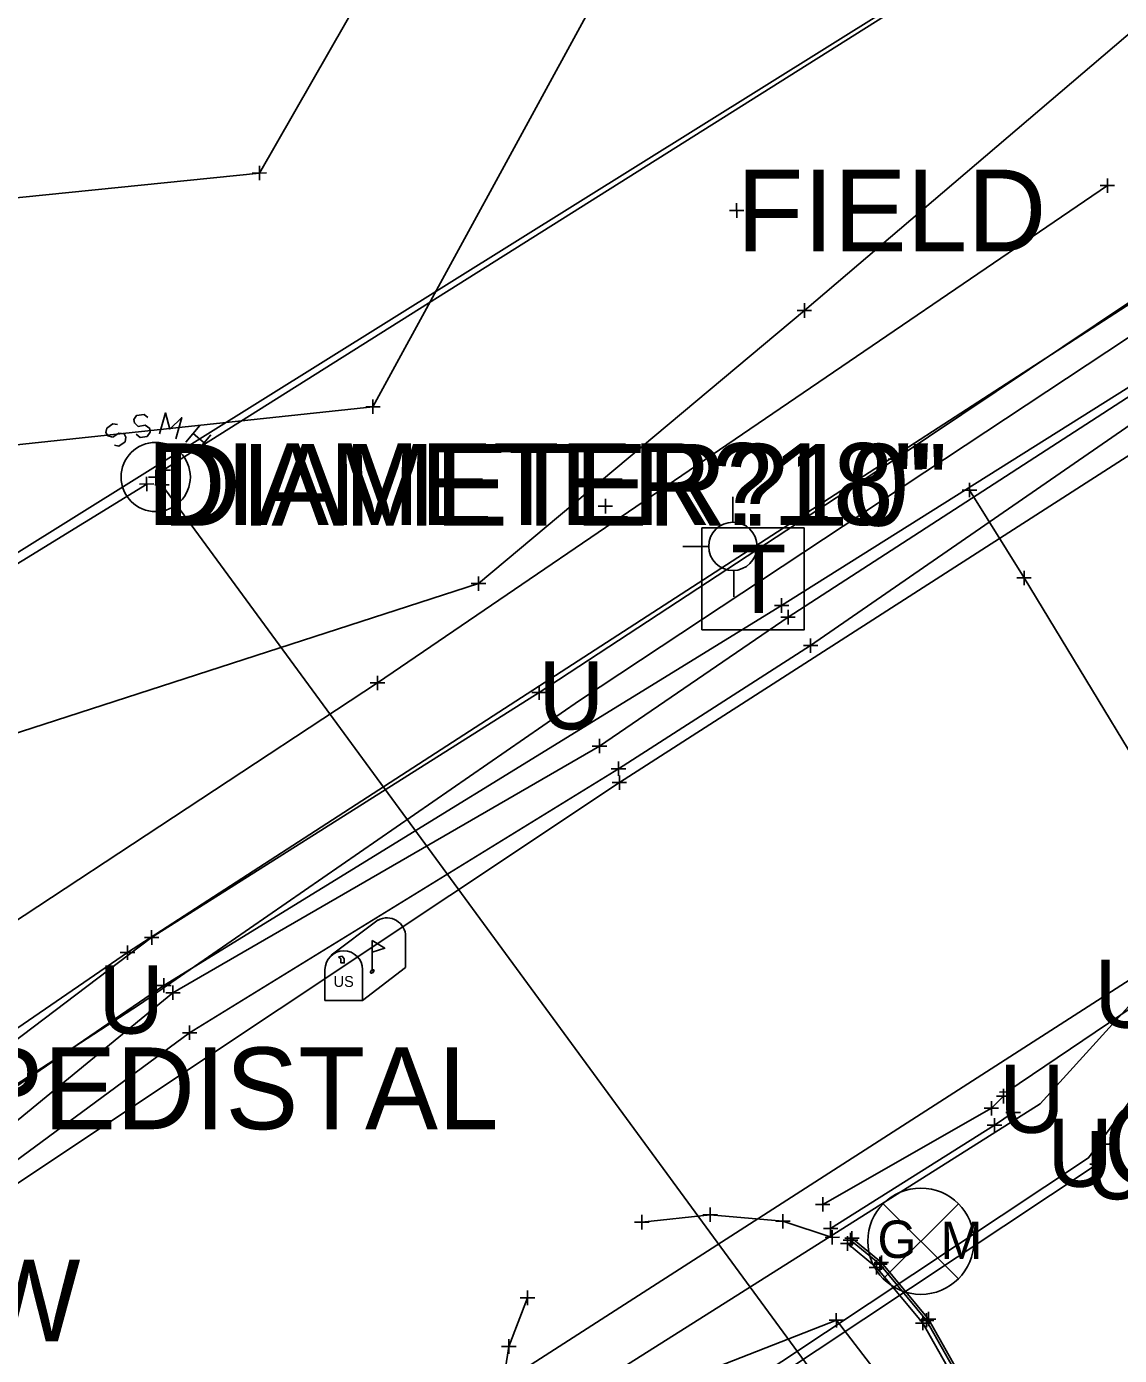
# Model space of a CAD drawing. Extents: x -1 to 1157254, y -1 to 2021979.
# Drawn here: x 1150680.9 to 1150777.1, y 2019897 to 2020014.1 of the extents above; entities that cross this region are included whole.
import ezdxf

# ---------------------------------------------------------------- set-up
doc = ezdxf.new("R2010")
doc.units = 0
for name, color, linetype in [('S_BUILDING_ANNOT', 7, 'Continuous'), ('S_CAL_CORNER_ANNOT', 7, 'Continuous'), ('S_CATCH_BASIN', 7, 'Continuous'), ('S_CATCH_BASIN_ANNOT', 7, 'Continuous'), ('S_CONTOUR_ANNOT', 7, 'Continuous'), ('S_CONTOUR_MAJOR', 7, 'Continuous'), ('S_CONTOUR_MINOR', 7, 'Continuous'), ('S_CROSS_DRAIN', 7, 'Continuous'), ('S_CTL_TABLE', 7, 'Continuous'), ('S_DRIVEWAY_ANNOT', 7, 'Continuous'), ('S_DROP_INLET', 7, 'Continuous'), ('S_DROP_INLET_ANNOT', 7, 'Continuous'), ('S_EDGE_BITUMINOUS_ANNOT', 7, 'Continuous'), ('S_EDGE_PAVEMENT', 7, 'Continuous'), ('S_EDGE_PAVEMENT_ANNOT', 7, 'Continuous'), ('S_ENV_CONSTRAINT', 7, 'Continuous'), ('S_FENCE', 7, 'Continuous'), ('S_GATE', 7, 'Continuous')]:
    doc.layers.add(name, color=color, linetype=linetype)

msp = doc.modelspace()

# ---------------------------------------------------------------- linework, layer by layer
at = {"layer": 'S_BUILDING_ANNOT'}
for p, q in [((1150775.44, 2020000.06), (1150776.71, 2020000.06)), ((1150776.08, 2019999.42), (1150776.07, 2020000.69)), ((1150776.08, 2020000.06), (1150776.08, 2020000.06)), ((1150742.78, 2019997.87), (1150744.05, 2019997.88)), ((1150743.42, 2019997.24), (1150743.41, 2019998.51)), ((1150743.41, 2019997.88), (1150743.41, 2019997.88)), ((1150692.89, 2019974.36), (1150692.89, 2019975.64)), ((1150692.89, 2019974.36), (1150692.89, 2019975.64)), ((1150691.44, 2019973.15), (1150691.43, 2019974.42)), ((1150691.44, 2019973.15), (1150691.43, 2019974.42)), ((1150691.59, 2019974.39), (1150692.87, 2019974.4)), ((1150692.23, 2019973.76), (1150692.23, 2019975.03)), ((1150692.23, 2019974.4), (1150692.23, 2019974.4)), ((1150692.25, 2019975), (1150693.53, 2019975)), ((1150692.25, 2019975), (1150693.53, 2019975)), ((1150692.78, 2019973.07), (1150692.77, 2019974.34)), ((1150692.78, 2019973.07), (1150692.77, 2019974.34)), ((1150692.89, 2019975), (1150692.89, 2019975)), ((1150692.89, 2019975), (1150692.89, 2019975)), ((1150690.8, 2019973.78), (1150692.07, 2019973.79)), ((1150690.8, 2019973.78), (1150692.07, 2019973.79)), ((1150691.44, 2019973.78), (1150691.44, 2019973.78)), ((1150691.44, 2019973.78), (1150691.44, 2019973.78)), ((1150692.14, 2019973.7), (1150693.41, 2019973.71)), ((1150692.14, 2019973.7), (1150693.41, 2019973.71)), ((1150692.78, 2019973.71), (1150692.78, 2019973.71)), ((1150692.78, 2019973.71), (1150692.78, 2019973.71)), ((1150763.28, 2019973.24), (1150764.56, 2019973.24)), ((1150763.92, 2019972.61), (1150763.92, 2019973.88)), ((1150763.92, 2019973.24), (1150763.92, 2019973.24)), ((1150731.21, 2019971.84), (1150732.48, 2019971.84)), ((1150731.85, 2019971.2), (1150731.85, 2019972.48)), ((1150731.85, 2019971.84), (1150731.85, 2019971.84)), ((1150768.74, 2019964.87), (1150768.73, 2019966.14)), ((1150768.1, 2019965.51), (1150769.37, 2019965.51)), ((1150768.74, 2019965.51), (1150768.74, 2019965.51)), ((1150747.37, 2019962.45), (1150747.37, 2019963.72)), ((1150746.74, 2019963.08), (1150748.01, 2019963.09)), ((1150747.37, 2019963.08), (1150747.37, 2019963.08)), ((1150747.94, 2019961.42), (1150747.94, 2019962.69)), ((1150747.3, 2019962.05), (1150748.57, 2019962.05)), ((1150747.94, 2019962.05), (1150747.94, 2019962.05)), ((1150749.93, 2019958.92), (1150749.93, 2019960.19)), ((1150749.3, 2019959.55), (1150750.57, 2019959.56)), ((1150749.93, 2019959.55), (1150749.93, 2019959.55)), ((1150711.77, 2019955.62), (1150711.77, 2019956.89)), ((1150711.13, 2019956.26), (1150712.41, 2019956.26)), ((1150711.77, 2019956.26), (1150711.77, 2019956.26)), ((1150730.69, 2019950.7), (1150731.96, 2019950.7)), ((1150731.33, 2019950.07), (1150731.32, 2019951.34)), ((1150731.32, 2019950.7), (1150731.32, 2019950.7)), ((1150732.37, 2019948.71), (1150733.64, 2019948.71)), ((1150733, 2019948.07), (1150733, 2019949.34)), ((1150733, 2019948.71), (1150733, 2019948.71)), ((1150732.45, 2019947.48), (1150733.72, 2019947.48)), ((1150733.09, 2019946.84), (1150733.09, 2019948.12)), ((1150733.09, 2019947.48), (1150733.09, 2019947.48)), ((1150689.74, 2019931.88), (1150689.74, 2019933.15)), ((1150689.11, 2019932.52), (1150690.38, 2019932.52)), ((1150689.74, 2019932.52), (1150689.74, 2019932.52)), ((1150692.3, 2019929.63), (1150693.58, 2019929.63)), ((1150692.94, 2019928.99), (1150692.94, 2019930.27)), ((1150692.94, 2019929.63), (1150692.94, 2019929.63)), ((1150693.75, 2019928.34), (1150693.75, 2019929.61)), ((1150693.12, 2019928.98), (1150694.39, 2019928.98)), ((1150693.75, 2019928.98), (1150693.75, 2019928.98)), ((1150695.22, 2019924.82), (1150695.21, 2019926.1)), ((1150694.58, 2019925.46), (1150695.85, 2019925.46)), ((1150695.21, 2019925.46), (1150695.21, 2019925.46)), ((1150766.58, 2019920.23), (1150767.85, 2019920.24)), ((1150766.93, 2019919.23), (1150766.93, 2019920.5)), ((1150767.22, 2019919.6), (1150767.22, 2019920.87)), ((1150767.22, 2019920.24), (1150767.22, 2019920.24)), ((1150765.86, 2019918.16), (1150765.86, 2019919.43)), ((1150766.29, 2019919.86), (1150767.56, 2019919.87)), ((1150766.93, 2019919.86), (1150766.93, 2019919.86)), ((1150767.77, 2019917.79), (1150767.77, 2019919.07)), ((1150765.22, 2019918.8), (1150766.49, 2019918.8)), ((1150765.86, 2019918.8), (1150765.86, 2019918.8)), ((1150766.12, 2019916.66), (1150766.12, 2019917.93)), ((1150767.14, 2019918.43), (1150768.41, 2019918.43)), ((1150767.77, 2019918.43), (1150767.77, 2019918.43)), ((1150765.48, 2019917.3), (1150766.76, 2019917.3)), ((1150766.12, 2019917.3), (1150766.12, 2019917.3)), ((1150775.11, 2019915.65), (1150776.38, 2019915.65)), ((1150775.74, 2019915.01), (1150775.74, 2019916.29)), ((1150775.74, 2019915.65), (1150775.74, 2019915.65)), ((1150775.16, 2019913.25), (1150775.16, 2019914.52)), ((1150774.52, 2019913.88), (1150775.79, 2019913.88)), ((1150775.16, 2019913.88), (1150775.16, 2019913.88)), ((1150750.99, 2019909.71), (1150750.99, 2019910.98)), ((1150741.08, 2019908.79), (1150741.08, 2019910.06)), ((1150750.35, 2019910.34), (1150751.63, 2019910.34)), ((1150750.99, 2019910.34), (1150750.99, 2019910.34)), ((1150734.42, 2019908.77), (1150735.69, 2019908.77)), ((1150735.06, 2019908.13), (1150735.06, 2019909.41)), ((1150735.06, 2019908.77), (1150735.06, 2019908.77)), ((1150740.44, 2019909.43), (1150741.71, 2019909.43)), ((1150741.08, 2019909.43), (1150741.08, 2019909.43)), ((1150746.86, 2019908.85), (1150748.13, 2019908.86)), ((1150747.49, 2019908.22), (1150747.49, 2019909.49)), ((1150747.49, 2019908.85), (1150747.49, 2019908.85)), ((1150751.69, 2019907.59), (1150751.69, 2019908.86)), ((1150751.05, 2019908.22), (1150752.32, 2019908.22)), ((1150751.2, 2019907.43), (1150752.47, 2019907.44)), ((1150751.69, 2019908.22), (1150751.69, 2019908.22)), ((1150751.84, 2019906.8), (1150751.83, 2019908.07)), ((1150751.84, 2019907.43), (1150751.84, 2019907.43)), ((1150752.94, 2019907.35), (1150754.21, 2019907.35)), ((1150753.19, 2019906.25), (1150753.19, 2019907.53)), ((1150753.45, 2019906.56), (1150753.45, 2019907.83)), ((1150753.58, 2019906.72), (1150753.57, 2019907.99)), ((1150753.57, 2019907.35), (1150753.57, 2019907.35)), ((1150752.56, 2019906.89), (1150753.83, 2019906.89)), ((1150752.81, 2019907.2), (1150754.08, 2019907.2)), ((1150753.19, 2019906.89), (1150753.19, 2019906.89)), ((1150753.45, 2019907.2), (1150753.45, 2019907.2)), ((1150755.39, 2019905.07), (1150756.66, 2019905.07)), ((1150755.53, 2019905.21), (1150756.8, 2019905.21)), ((1150755.74, 2019904.15), (1150755.74, 2019905.42)), ((1150756.02, 2019904.43), (1150756.02, 2019905.71)), ((1150756.02, 2019905.07), (1150756.02, 2019905.07)), ((1150756.16, 2019904.58), (1150756.16, 2019905.85)), ((1150756.16, 2019905.21), (1150756.16, 2019905.21)), ((1150755.1, 2019904.78), (1150756.37, 2019904.79)), ((1150755.74, 2019904.78), (1150755.74, 2019904.78)), ((1150724.98, 2019901.46), (1150724.98, 2019902.74)), ((1150724.35, 2019902.1), (1150725.62, 2019902.1)), ((1150724.98, 2019902.1), (1150724.98, 2019902.1)), ((1150759.82, 2019899.25), (1150759.82, 2019900.53)), ((1150760.15, 2019899.48), (1150760.15, 2019900.76)), ((1150760.32, 2019899.6), (1150760.32, 2019900.87)), ((1150759.18, 2019899.89), (1150760.46, 2019899.89)), ((1150759.52, 2019900.12), (1150760.79, 2019900.12)), ((1150759.68, 2019900.23), (1150760.95, 2019900.24)), ((1150759.82, 2019899.89), (1150759.82, 2019899.89)), ((1150760.15, 2019900.12), (1150760.15, 2019900.12)), ((1150760.32, 2019900.23), (1150760.32, 2019900.23)), ((1150723.34, 2019897.18), (1150723.34, 2019898.46)), ((1150722.7, 2019897.82), (1150723.98, 2019897.82)), ((1150723.34, 2019897.82), (1150723.34, 2019897.82))]:
    msp.add_line(p, q, dxfattribs=at)
at = {"layer": 'S_CAL_CORNER_ANNOT'}
for p, q in [((1150756.33, 2019903.78), (1150762.95, 2019910.39)), ((1150756.33, 2019910.39), (1150762.95, 2019903.78))]:
    msp.add_line(p, q, dxfattribs=at)
for points in [[(1150827.62, 2020008.19), (1150733.09, 2019947.48), (1150628.16, 2019877.65), (1150500.75, 2019790.99), (1150424.78, 2019737.67), (1150355.4, 2019749.66)], [(1150880.61, 2019997.07), (1150845.23, 2019974.01), (1150778.48, 2019930.4), (1150712.23, 2019887.84), (1150693.16, 2019874.92), (1150703.17, 2019846.82)]]:
    msp.add_lwpolyline(points, dxfattribs=at)
msp.add_circle((1150759.64, 2019907.09), 4.68, dxfattribs=at)
at = {"layer": 'S_CATCH_BASIN'}
for p, q in [((1150743.07, 2019970.4), (1150743.07, 2019972.65)), ((1150740.98, 2019968.27), (1150738.66, 2019968.27)), ((1150743.15, 2019963.86), (1150743.15, 2019966.18))]:
    msp.add_line(p, q, dxfattribs=at)
msp.add_circle((1150743.08, 2019968.29), 2.13, dxfattribs=at)
at = {"layer": 'S_CATCH_BASIN_ANNOT'}
msp.add_lwpolyline([(1150740.35, 2019960.93), (1150740.35, 2019969.92), (1150749.35, 2019969.92), (1150749.35, 2019960.93)], close=True, dxfattribs=at)
at = {"layer": 'S_CONTOUR_ANNOT'}
for points in [[(1150857.08, 2020031.73), (1150832.22, 2020016.43), (1150747.37, 2019963.08), (1150692.94, 2019929.63), (1150639.49, 2019893), (1150583.9, 2019856.96), (1150484.25, 2019790.85), (1150433.08, 2019750.74), (1150355.8, 2019695.65), (1150341.28, 2019681.73), (1150287.94, 2019641.18), (1150216.41, 2019587.25), (1150034.4, 2019445.88), (1149979.98, 2019405.6), (1149934.92, 2019374.11), (1149784.56, 2019258.12)], [(1150776.08, 2020000.06), (1150711.77, 2019956.26), (1150627.27, 2019900.66), (1150578.77, 2019864.96), (1150479.12, 2019798.68), (1150423.47, 2019764.16), (1150358.5, 2019722.73), (1150313.96, 2019690.01), (1150273.95, 2019661.03), (1150225.64, 2019623.26), (1150033.5, 2019468.9), (1149971.69, 2019423.78), (1149931.59, 2019393.98), (1149688.42, 2019230.92)], [(1150763.92, 2019973.24), (1150768.74, 2019965.51), (1150784.44, 2019939.62), (1150789.99, 2019930.58)]]:
    msp.add_lwpolyline(points, dxfattribs=at)
at = {"layer": 'S_CONTOUR_MINOR'}
for p, q in [((1150687.91, 2019978.7), (1150687.83, 2019978.31)), ((1150688.45, 2019979.08), (1150687.91, 2019978.7)), ((1150688.87, 2019979.01), (1150688.45, 2019979.08)), ((1150694.88, 2019977.46), (1150696.12, 2019978.93)), ((1150687.83, 2019978.31), (1150688.02, 2019978.04)), ((1150688.02, 2019978.04), (1150688.45, 2019977.92)), ((1150688.45, 2019977.92), (1150688.99, 2019978.27)), ((1150688.99, 2019978.27), (1150689.46, 2019978.19)), ((1150689.53, 2019977.5), (1150688.99, 2019977.11)), ((1150689.46, 2019978.19), (1150689.61, 2019977.92)), ((1150689.61, 2019977.92), (1150689.53, 2019977.5)), ((1150695.54, 2019978.23), (1150696.5, 2019977.42)), ((1150697.09, 2019978.12), (1150695.85, 2019976.64)), ((1150688.99, 2019977.11), (1150688.6, 2019977.19))]:
    msp.add_line(p, q, dxfattribs=at)
for points in [[(1150811.96, 2020050.1), (1150624.41, 2019933.02)], [(1150812.38, 2020050.22), (1150692.89, 2019975)], [(1150691.55, 2019979.63), (1150691.2, 2019979.9), (1150690.54, 2019979.82), (1150690.31, 2019979.47), (1150690.35, 2019979.16), (1150690.69, 2019978.85), (1150691.31, 2019978.97), (1150691.7, 2019978.66), (1150691.74, 2019978.35), (1150691.47, 2019977.96), (1150690.85, 2019977.88), (1150690.5, 2019978.16)], [(1150693.99, 2019977.77), (1150694.53, 2019979.63), (1150693.48, 2019978.62), (1150693.1, 2019980.05), (1150692.55, 2019978.19)], [(1150691.44, 2019973.78), (1150624.76, 2019932.8)], [(1150692.78, 2019973.71), (1150752.69, 2019892.04)]]:
    msp.add_lwpolyline(points, dxfattribs=at)
msp.add_circle((1150692.23, 2019974.4), 3.05, dxfattribs=at)
at = {"layer": 'S_CROSS_DRAIN'}
for p, q in [((1150707.69, 2019932.28), (1150711.82, 2019935.39)), ((1150711.3, 2019933.57), (1150711.3, 2019930.85)), ((1150714.25, 2019933.91), (1150714.25, 2019931.2)), ((1150707.13, 2019931.01), (1150707.13, 2019928.29)), ((1150710.46, 2019928.29), (1150714.25, 2019931.2)), ((1150710.46, 2019931.01), (1150710.46, 2019928.29)), ((1150707.13, 2019928.29), (1150710.46, 2019928.29))]:
    msp.add_line(p, q, dxfattribs=at)
for points in [[(1150711.3, 2019933.57), (1150712.41, 2019932.9), (1150711.3, 2019932.56)], [(1150708.32, 2019932.12), (1150708.54, 2019931.98), (1150708.54, 2019931.6), (1150708.84, 2019931.6), (1150708.84, 2019931.96), (1150708.65, 2019932.2), (1150708.32, 2019932.15)]]:
    msp.add_lwpolyline(points, dxfattribs=at)
for centre, end in [((1150712.59, 2019933.91), 117.5718), ((1150708.8, 2019931.01), 180)]:
    msp.add_arc(centre, 1.66, 0, end, dxfattribs=at)
msp.add_ellipse((1150711.3, 2019930.85), major_axis=(0.145, 0.132), ratio=0.564646, dxfattribs=at)
at = {"layer": 'S_CTL_TABLE'}
for p, q in [((1150700.73, 2020001.17), (1150702, 2020001.18)), ((1150701.36, 2020000.54), (1150701.36, 2020001.81)), ((1150701.36, 2020001.17), (1150701.36, 2020001.17)), ((1150749.39, 2019988.43), (1150749.38, 2019989.7)), ((1150748.75, 2019989.07), (1150750.02, 2019989.07)), ((1150749.39, 2019989.07), (1150749.39, 2019989.07)), ((1150711.37, 2019979.95), (1150711.36, 2019981.23)), ((1150710.73, 2019980.59), (1150712, 2019980.59)), ((1150711.37, 2019980.59), (1150711.37, 2019980.59)), ((1150757.39, 2019975.33), (1150757.39, 2019976.6)), ((1150756.75, 2019975.96), (1150758.02, 2019975.96)), ((1150757.39, 2019975.96), (1150757.39, 2019975.96)), ((1150720.02, 2019965.01), (1150721.3, 2019965.01)), ((1150720.66, 2019964.37), (1150720.66, 2019965.64)), ((1150720.66, 2019965.01), (1150720.66, 2019965.01)), ((1150725.38, 2019955.41), (1150726.65, 2019955.41)), ((1150726.02, 2019954.78), (1150726.02, 2019956.05)), ((1150726.02, 2019955.41), (1150726.02, 2019955.41)), ((1150691.88, 2019933.21), (1150691.87, 2019934.48)), ((1150691.24, 2019933.84), (1150692.51, 2019933.84)), ((1150691.87, 2019933.84), (1150691.87, 2019933.84)), ((1150752.2, 2019899.5), (1150752.19, 2019900.77)), ((1150751.56, 2019900.14), (1150752.83, 2019900.14)), ((1150752.2, 2019900.14), (1150752.2, 2019900.14))]:
    msp.add_line(p, q, dxfattribs=at)
at = {"layer": 'S_DRIVEWAY_ANNOT'}
for points in [[(1150855.79, 2020029.67), (1150831.35, 2020015.2), (1150787.83, 2019987.87), (1150747.94, 2019962.05), (1150731.32, 2019950.7), (1150693.75, 2019928.98), (1150675.33, 2019913.88), (1150662.78, 2019906.81)], [(1150856.47, 2020028.31), (1150832.96, 2020013.32), (1150788.5, 2019986.18), (1150749.93, 2019959.55), (1150733, 2019948.71), (1150695.21, 2019925.46), (1150676.27, 2019911.51), (1150664.29, 2019905.18)], [(1150766.93, 2019919.86), (1150765.86, 2019918.8), (1150750.99, 2019910.34)], [(1150767.77, 2019918.43), (1150766.12, 2019917.3), (1150751.69, 2019908.22)]]:
    msp.add_lwpolyline(points, dxfattribs=at)
at = {"layer": 'S_DROP_INLET'}
for points in [[(1150831.49, 2020022.11), (1150729.58, 2019954.73), (1150690.81, 2019927.93), (1150657.92, 2019906.59), (1150452.8, 2019766.7), (1150415.16, 2019745.86)], [(1150852.18, 2019973.05), (1150778.54, 2019928.45), (1150770.16, 2019919.18), (1150703.8, 2019877.29), (1150608.63, 2019809.12), (1150513.43, 2019739.89), (1150405.92, 2019663.65), (1150352.2, 2019622.72), (1150343.81, 2019614.74), (1150336.72, 2019606.98), (1150314.89, 2019591.84), (1150193.25, 2019498.28), (1150112.69, 2019435.49), (1150059.59, 2019406.16), (1150037.88, 2019389.79), (1149962.99, 2019329.91), (1149914.05, 2019297.4), (1149863.26, 2019256.98)], [(1150853.56, 2019969.99), (1150781.71, 2019924.44), (1150774.41, 2019914.43), (1150697.13, 2019863.12), (1150609.24, 2019805.57), (1150516.58, 2019735.98), (1150408.74, 2019655.56), (1150359.48, 2019622.09), (1150352.77, 2019615.32), (1150355.2, 2019603.6), (1150359.35, 2019593.87)]]:
    msp.add_lwpolyline(points, dxfattribs=at)
at = {"layer": 'S_DROP_INLET_ANNOT'}
msp.add_lwpolyline([(1150783.94, 2019931.55), (1150767.22, 2019920.24)], dxfattribs=at)
at = {"layer": 'S_EDGE_BITUMINOUS_ANNOT'}
for points in [[(1150769.01, 2020065.16), (1150721.21, 2020035.77), (1150701.36, 2020001.17), (1150655.3, 2019996.5), (1150642.21, 2019974.87), (1150615.41, 2019959.15), (1150586.28, 2019932.71)], [(1150780.18, 2020046.65), (1150731.01, 2020016.6), (1150711.37, 2019980.59), (1150665.89, 2019975.73), (1150652.68, 2019953.36), (1150630.56, 2019938.88), (1150601.87, 2019912.49)], [(1150789.87, 2020023.58), (1150749.39, 2019989.07), (1150720.66, 2019965.01), (1150679.31, 2019951.64), (1150664.04, 2019935.25), (1150646.88, 2019923.06)], [(1150798.77, 2020003.69), (1150757.39, 2019975.96), (1150726.02, 2019955.41), (1150691.87, 2019933.84), (1150671.94, 2019918.78), (1150661.69, 2019911.24)], [(1150727.8, 2019892.61), (1150728.52, 2019870.64), (1150733.36, 2019847.61), (1150741.18, 2019817), (1150751.17, 2019821.99), (1150747.11, 2019842.42), (1150742.99, 2019865.52), (1150738.92, 2019894.93), (1150752.2, 2019900.14), (1150759.36, 2019890.79), (1150761.51, 2019879.32), (1150756.5, 2019867.28), (1150753.25, 2019851), (1150759.21, 2019831.44)]]:
    msp.add_lwpolyline(points, dxfattribs=at)
at = {"layer": 'S_EDGE_PAVEMENT'}
for points in [[(1150753.19, 2019906.89), (1150755.74, 2019904.78), (1150759.82, 2019899.89), (1150764.03, 2019892.4), (1150766.61, 2019883.5), (1150766.33, 2019877.07), (1150763.93, 2019870.26), (1150759.61, 2019863.3), (1150757.04, 2019856.32), (1150756.61, 2019848.35), (1150758.8, 2019841.04), (1150762.98, 2019833.79), (1150774.66, 2019817.17)], [(1150753.45, 2019907.2), (1150756.02, 2019905.07), (1150760.15, 2019900.12), (1150764.41, 2019892.56), (1150767.01, 2019883.55), (1150766.72, 2019877), (1150764.29, 2019870.09), (1150759.97, 2019863.12), (1150757.44, 2019856.24), (1150757.02, 2019848.4), (1150759.17, 2019841.2), (1150763.31, 2019834), (1150774.99, 2019817.4)]]:
    msp.add_lwpolyline(points, dxfattribs=at)
at = {"layer": 'S_EDGE_PAVEMENT_ANNOT'}
msp.add_lwpolyline([(1150753.57, 2019907.35), (1150756.16, 2019905.21), (1150760.32, 2019900.23), (1150764.59, 2019892.63), (1150767.21, 2019883.57), (1150766.92, 2019876.96), (1150764.47, 2019870), (1150760.15, 2019863.04), (1150757.63, 2019856.2), (1150757.22, 2019848.43), (1150759.36, 2019841.28), (1150763.48, 2019834.11), (1150775.15, 2019817.52)], dxfattribs=at)
at = {"layer": 'S_ENV_CONSTRAINT'}
for points in [[(1150735.06, 2019908.77), (1150741.08, 2019909.43), (1150747.49, 2019908.85), (1150751.84, 2019907.43)], [(1150724.98, 2019902.1), (1150723.34, 2019897.82), (1150722.16, 2019890.25), (1150722.06, 2019888.43)]]:
    msp.add_lwpolyline(points, dxfattribs=at)
at = {"layer": 'S_FENCE'}
for points in [[(1150830.5, 2020023.61), (1150689.74, 2019932.52), (1150654.37, 2019908.24), (1150454.61, 2019773.54), (1150421.5, 2019756.1), (1150406.6, 2019759.37)], [(1150775.16, 2019913.88), (1150697.15, 2019862.05), (1150611.54, 2019805.47), (1150516.86, 2019735.37), (1150402.98, 2019659.79), (1150352.98, 2019622.15), (1150350.25, 2019606.72), (1150331.34, 2019598.55), (1150196.24, 2019490.87), (1150043.62, 2019380.11), (1149966.77, 2019324.72), (1149934.21, 2019308.48), (1149916.33, 2019289.12), (1149866.68, 2019250.91)]]:
    msp.add_lwpolyline(points, dxfattribs=at)

# ---------------------------------------------------------------- texts
at = {"layer": 'S_BUILDING_ANNOT'}
for s, p in [('DIAMETER?18"', (1150691.44, 2019970.18)), ('DIAMETER?10"', (1150692.78, 2019970.11))]:
    msp.add_text(s, height=7.2, dxfattribs=at).set_placement(p)
at = {"layer": 'S_CAL_CORNER_ANNOT'}
for s, p in [('G', (1150755.82, 2019905.62)), ('M', (1150761.38, 2019905.52))]:
    msp.add_text(s, height=3.3, dxfattribs=at).set_placement(p)
at = {"layer": 'S_CATCH_BASIN_ANNOT'}
msp.add_text('T', height=6, dxfattribs=at).set_placement((1150742.91, 2019962.43))
at = {"layer": 'S_CONTOUR_MAJOR'}
for p in [(1150725.95, 2019952.18), (1150774.91, 2019925.9), (1150687.18, 2019925.38), (1150766.53, 2019916.64), (1150770.78, 2019911.89), (1150774.07, 2019910.79)]:
    msp.add_text('U', height=6, dxfattribs=at).set_placement(p)
at = {"layer": 'S_CROSS_DRAIN'}
msp.add_text('US', height=0.96, dxfattribs=at).set_placement((1150707.9, 2019929.49))
at = {"layer": 'S_GATE'}
for s, p in [('FIELD', (1150743.41, 2019994.28)), ('3\'X18"X18" CONC PEDISTAL', (1150593.91, 2019916.96)), ('CONC DW', (1150775.74, 2019912.05)), ('GR DW', (1150652.44, 2019898.27))]:
    msp.add_text(s, height=7.2, dxfattribs=at).set_placement(p)

doc.saveas('drawing.dxf')
